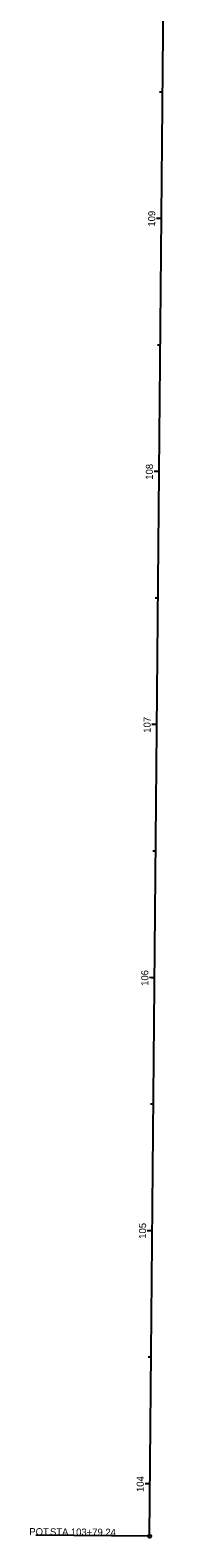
# Model space of a CAD drawing. Extents: x 177110 to 177558, y 286252 to 294117.
# Drawn here: x 177110 to 177168, y 286252 to 286847 of the extents above; entities that cross this region are included whole.
import ezdxf

# ---------------------------------------------------------------- set-up
doc = ezdxf.new("R2010")
doc.units = 0
for name, color, linetype in [('GE_X_Alignment_500_Cardinal_Points', 7, 'Continuous'), ('GE_X_Alignment_500_Stations', 7, 'Continuous'), ('RW_X_CL', 7, 'Continuous'), ('RW_X_CL_100_Cardinal_Points', 7, 'Continuous'), ('RW_X_CL_100_Stations', 7, 'Continuous')]:
    doc.layers.add(name, color=color, linetype=linetype)

msp = doc.modelspace()

# ---------------------------------------------------------------- linework, layer by layer
at = {"layer": 'GE_X_Alignment_500_Cardinal_Points'}
msp.add_line((177157.11, 286252.3), (177112.12, 286252.7), dxfattribs=at)
msp.add_circle((177157.11, 286252.3), 0.6, dxfattribs=at)
at = {"layer": 'GE_X_Alignment_500_Stations'}
for p, q in [((177161.83, 286773.04), (177160.63, 286773.05)), ((177160.92, 286673.04), (177159.72, 286673.05)), ((177160.02, 286573.05), (177158.82, 286573.06)), ((177159.11, 286473.05), (177157.91, 286473.06)), ((177158.21, 286373.05), (177156.21, 286373.07)), ((177157.3, 286273.06), (177156.1, 286273.07))]:
    msp.add_line(p, q, dxfattribs=at)
at = {"layer": 'RW_X_CL'}
msp.add_line((177157.11, 286252.3), (177168.31, 287489.01), dxfattribs=at)
at = {"layer": 'RW_X_CL_100_Cardinal_Points'}
msp.add_line((177157.11, 286252.3), (177112.12, 286252.7), dxfattribs=at)
msp.add_circle((177157.11, 286252.3), 0.6, dxfattribs=at)
at = {"layer": 'RW_X_CL_100_Stations'}
for p, q in [((177162.28, 286823.04), (177161.08, 286823.05)), ((177161.83, 286773.04), (177159.83, 286773.06)), ((177161.37, 286723.04), (177160.17, 286723.05)), ((177160.92, 286673.04), (177158.92, 286673.06)), ((177160.47, 286623.04), (177159.27, 286623.06)), ((177160.02, 286573.05), (177158.02, 286573.06)), ((177159.56, 286523.05), (177158.36, 286523.06)), ((177159.11, 286473.05), (177157.11, 286473.07)), ((177158.66, 286423.05), (177157.46, 286423.06)), ((177158.21, 286373.05), (177156.21, 286373.07)), ((177157.75, 286323.06), (177156.55, 286323.07)), ((177157.3, 286273.06), (177155.3, 286273.08))]:
    msp.add_line(p, q, dxfattribs=at)

# ---------------------------------------------------------------- texts
at = {"layer": 'GE_X_Alignment_500_Cardinal_Points'}
for s, p in [('POT', (177109.5, 286252.76)), (' STA. ', (177116.63, 286252.7)), ('103+79.24', (177125.95, 286252.61))]:
    msp.add_text(s, height=2.8, rotation=359.48145, dxfattribs=at).set_placement(p)
at = {"layer": 'GE_X_Alignment_500_Stations'}
msp.add_text('105', height=2.8, rotation=89.48145, dxfattribs=at).set_placement((177155.68, 286369.87))
at = {"layer": 'RW_X_CL_100_Cardinal_Points'}
for s, p in [('POT', (177109.5, 286252.76)), (' STA. ', (177116.63, 286252.7)), ('103+79.24', (177125.95, 286252.61))]:
    msp.add_text(s, height=2.8, rotation=359.48145, dxfattribs=at).set_placement(p)
at = {"layer": 'RW_X_CL_100_Stations'}
for s, p in [('109', (177159.3, 286769.84)), ('108', (177158.39, 286669.82)), ('107', (177157.49, 286569.83)), ('106', (177156.58, 286469.82)), ('105', (177155.68, 286369.87)), ('104', (177154.77, 286269.8))]:
    msp.add_text(s, height=2.8, rotation=89.48145, dxfattribs=at).set_placement(p)

doc.saveas('drawing.dxf')
